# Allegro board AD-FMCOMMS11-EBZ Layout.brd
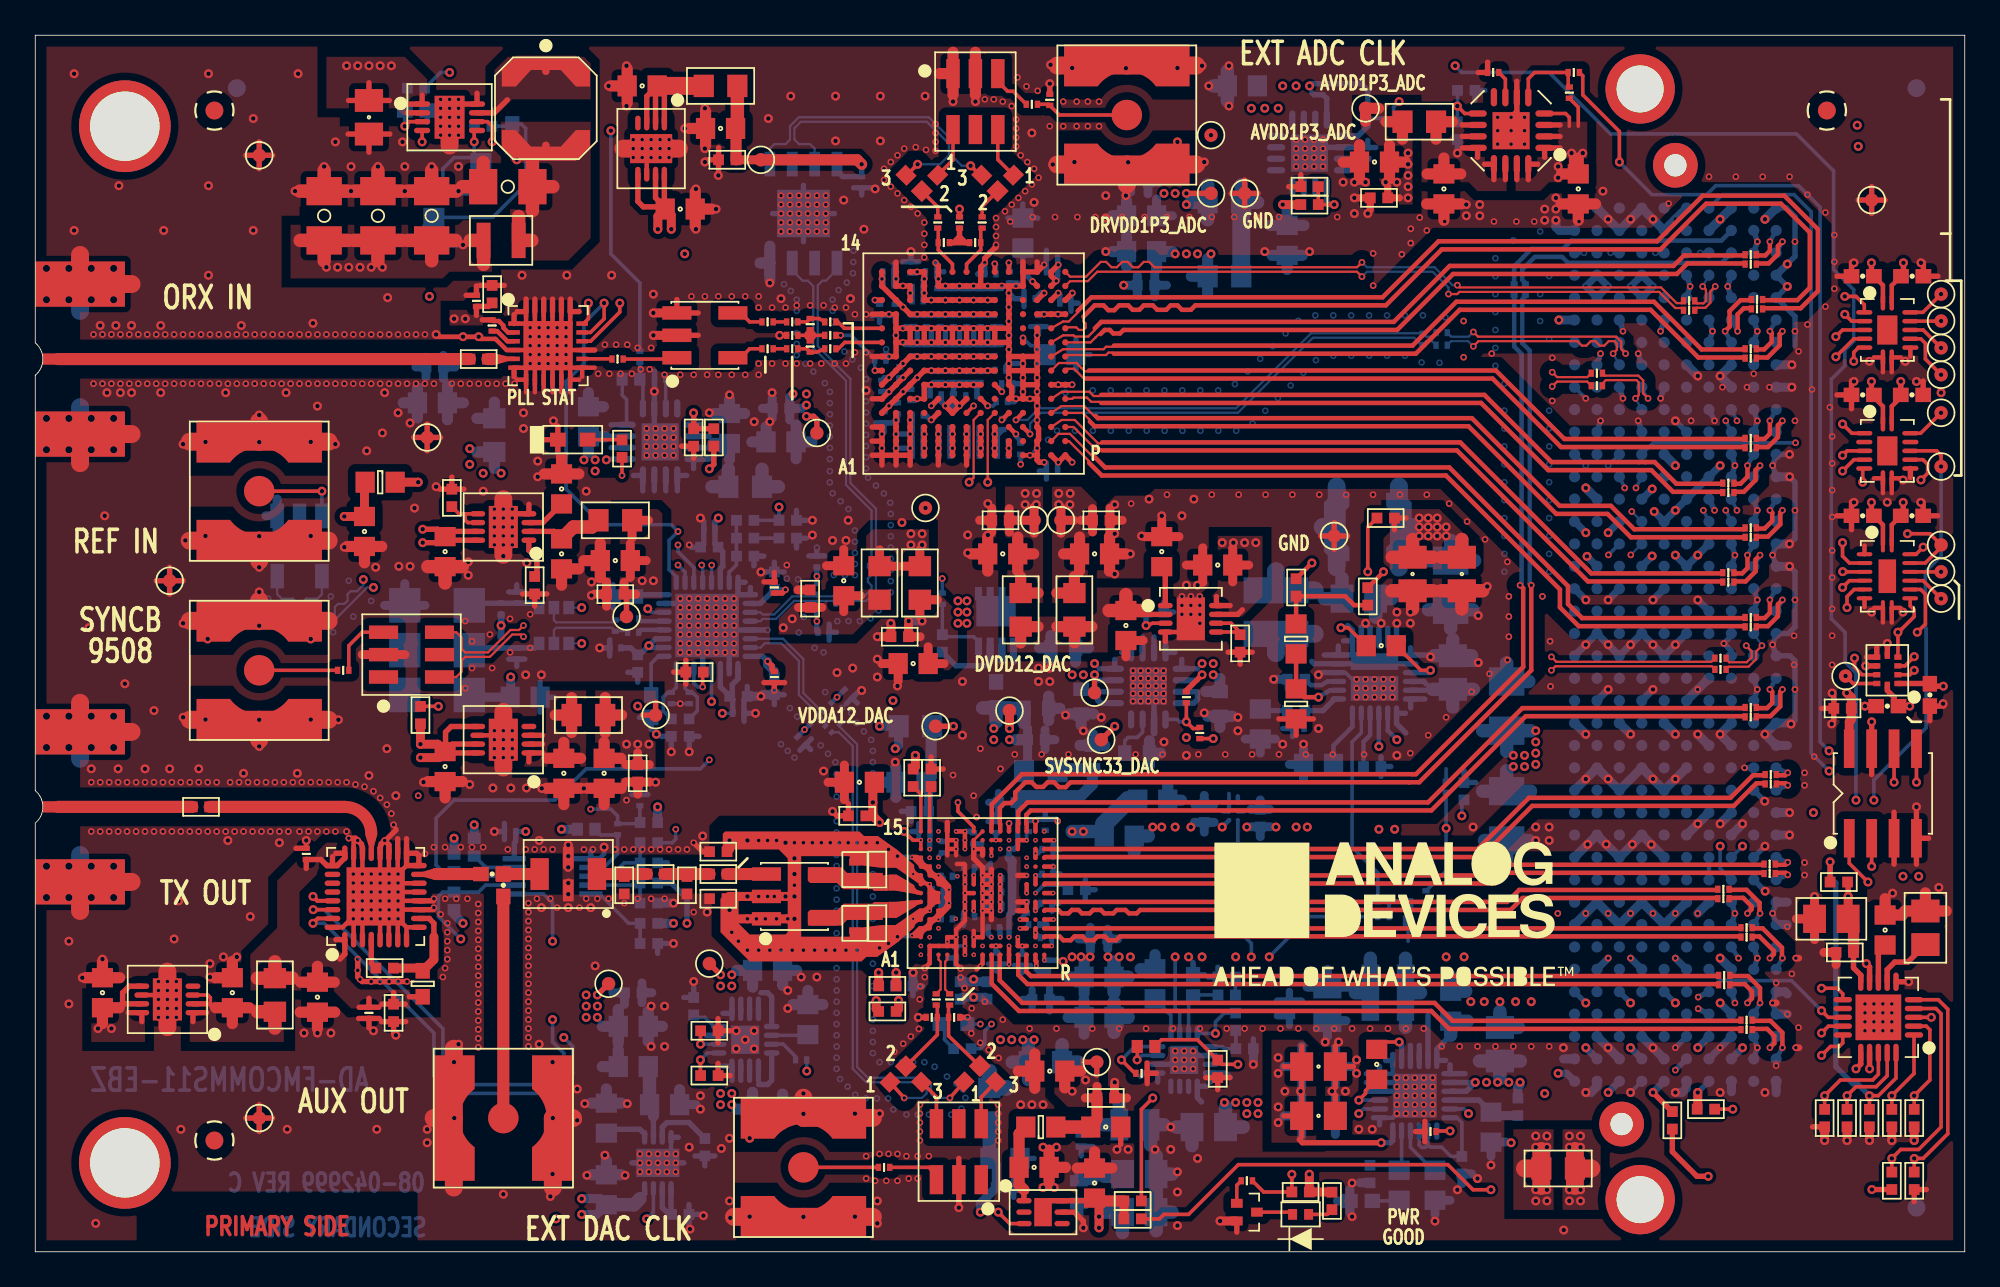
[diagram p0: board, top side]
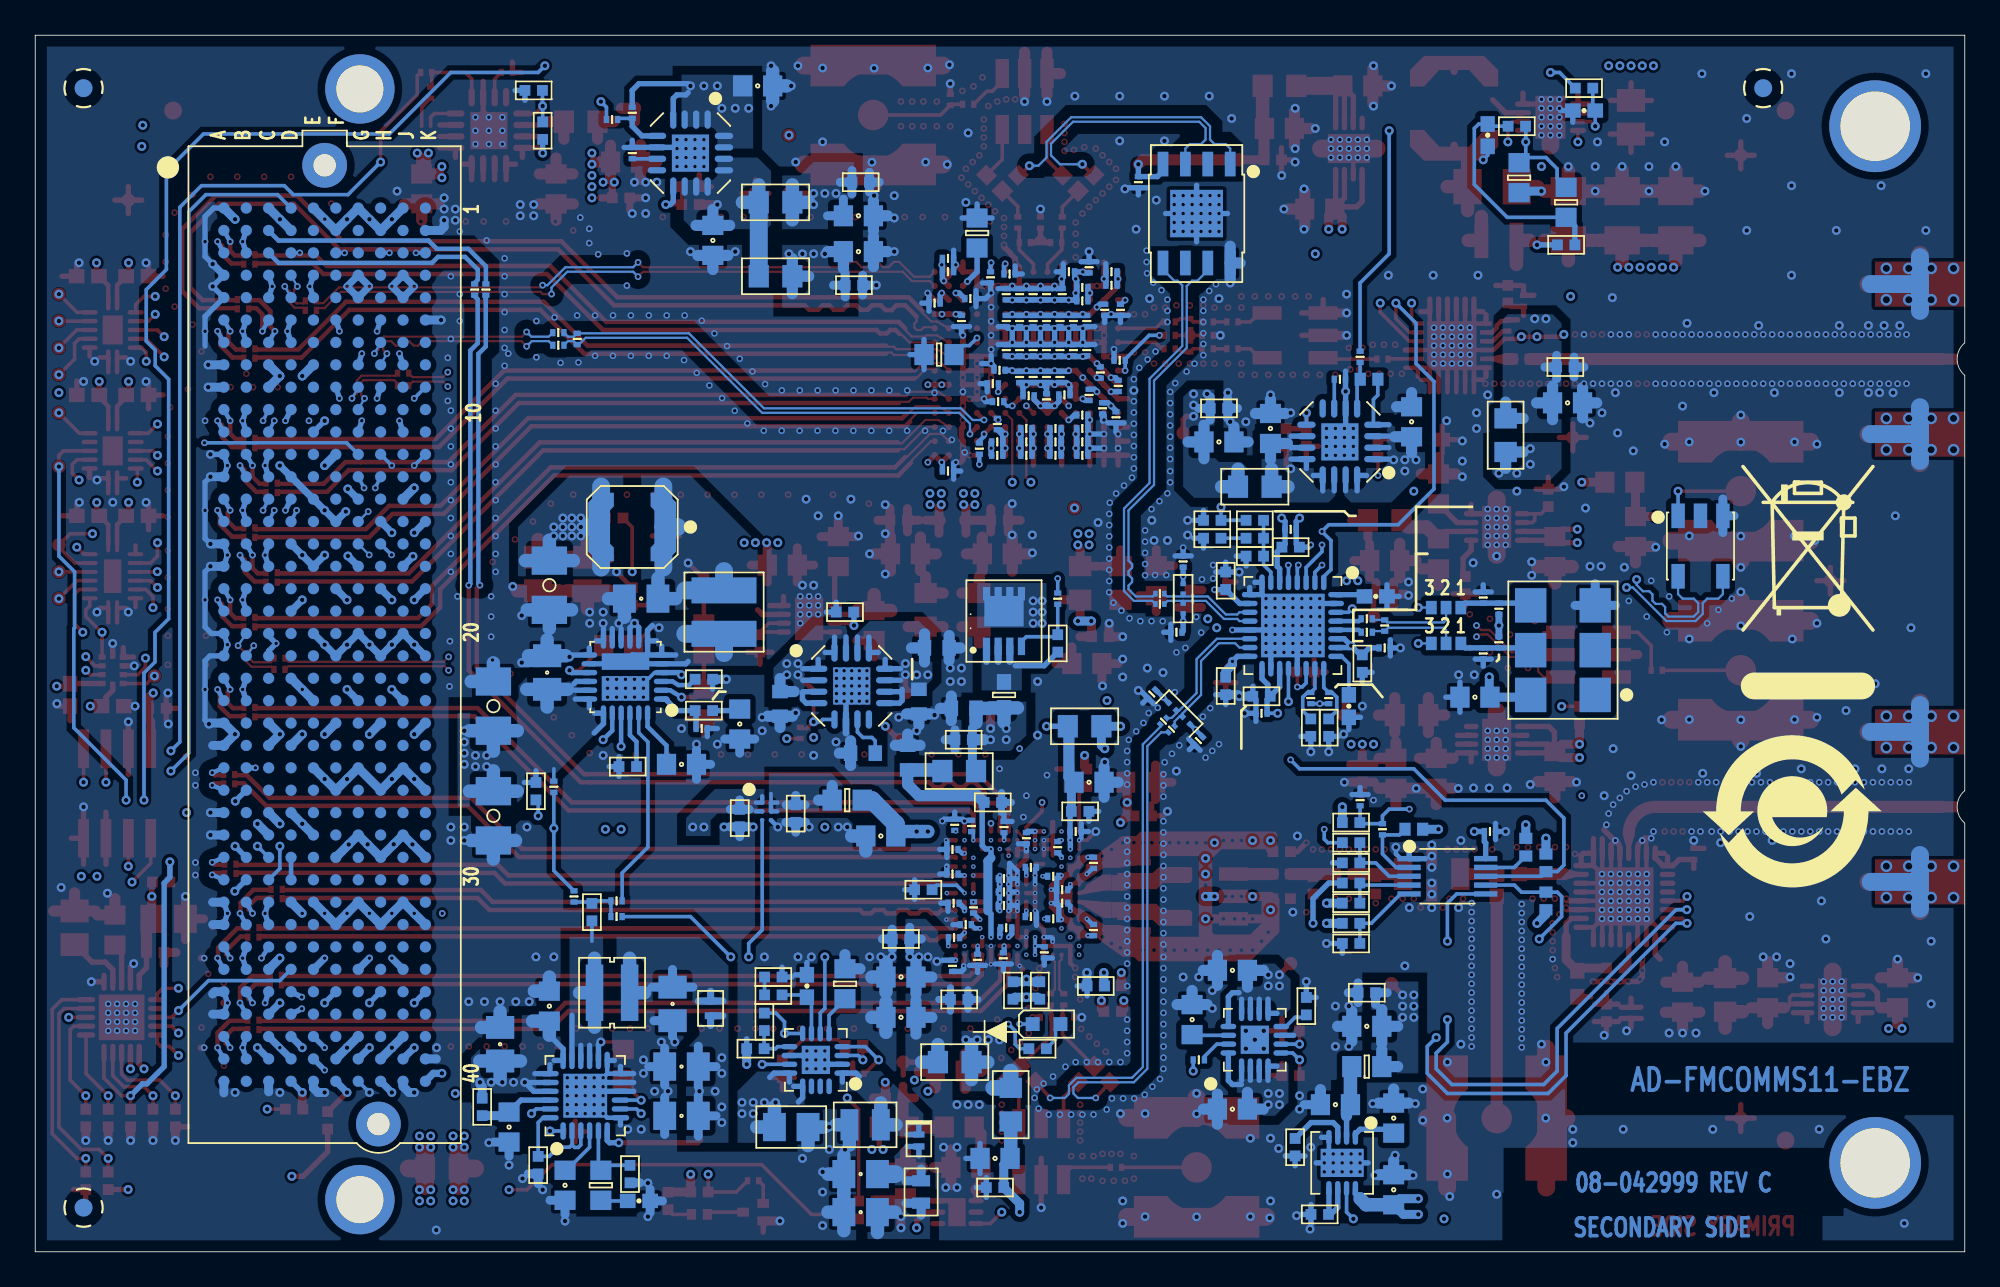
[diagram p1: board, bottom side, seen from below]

Outline 109.42 x 69 mm; copper layers: TOP, L2_GROUND, L3_SIGNAL, L4_GROUND, L5_POWER, L6_GROUND, L7_GROUND, L8_POWER, L9_GROUND, L10_SIGNAL, L11_GROUND, BOTTOM. Coordinates in mm from the lower left corner of the outline.
Outline path: 0,69 109.42,69 109.42,0 0,0 0,24.31 arc(0.43,25.23) 0,26.15 0,49.71 arc(0.43,50.63) 0,51.55 0,69

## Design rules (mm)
constraint set DEFAULT: min track width 0.203
net group ADC_CLK: nets ADC_CLK_N ADC_CLK_P
net group ADC_CLK2: nets UNNAMED_28_HMC361_I1297_OUT UNNAMED_28_HMC361_I1297_OUTN
net group ADC_CLK3: nets UNNAMED_28_ADF4355_I1290_RFOU_1 UNNAMED_28_ADF4355_I1290_RFOUTA
net group DAC_CLK3: nets UNNAMED_28_ADF4355_I1290_RFOU_2 UNNAMED_28_ADF4355_I1290_RFOUTB
net group DAC_CLK_N: nets DAC_CLK_N UNNAMED_28_CAP_I1301_N1
net group DAC_CLK_P: nets DAC_CLK_P UNNAMED_28_CAP_I1302_N1
net group DAC_OUT: nets DAC_OUT_N DAC_OUT_P
net group DIVCLK_N: nets DIVCLK_N UNNAMED_27_CAP_I500_N2
net group DIVCLK_P: nets DIVCLK_P UNNAMED_27_CAP_I499_N2
net group DOUTA_N: nets DOUTA_N UNNAMED_27_CAP_I377_N2
net group DOUTA_P: nets DOUTA_P UNNAMED_27_CAP_I378_N2
net group DOUTB_N: nets DOUTB_N UNNAMED_27_CAP_I363_N2
net group DOUTB_P: nets DOUTB_P UNNAMED_27_CAP_I362_N2
net group DOUTC_N: nets DOUTC_N UNNAMED_27_CAP_I364_N2
net group DOUTC_P: nets DOUTC_P UNNAMED_27_CAP_I365_N2
net group DOUTD_N: nets DOUTD_N UNNAMED_27_CAP_I366_N2
net group DOUTD_P: nets DOUTD_P UNNAMED_27_CAP_I367_N2
net group DOUTE_N: nets DOUTE_N UNNAMED_27_CAP_I373_N2
net group DOUTE_P: nets DOUTE_P UNNAMED_27_CAP_I374_N2
net group DOUTF_N: nets DOUTF_N UNNAMED_27_CAP_I369_N2
net group DOUTF_P: nets DOUTF_P UNNAMED_27_CAP_I368_N2
net group DOUTG_N: nets DOUTG_N UNNAMED_27_CAP_I376_N2
net group DOUTG_P: nets DOUTG_P UNNAMED_27_CAP_I375_N2
net group DOUTH_N: nets DOUTH_N UNNAMED_27_CAP_I371_N2
net group DOUTH_P: nets DOUTH_P UNNAMED_27_CAP_I370_N2
net group DP1: nets UNNAMED_28_CAP_I1359_N2 UNNAMED_28_CAP_I1360_N2
net group DP2: nets UNNAMED_28_CAP_I1372_N2 UNNAMED_28_CAP_I1373_N2
net group DP3: nets UNNAMED_28_NC3PJMPR_I1389_B UNNAMED_28_NC3PJMPR_I1390_B
net group DSYNC_P1: nets DSYNC_P1_N DSYNC_P1_P
net group DUT_DSYNC: nets DUT_DSYNC_N DUT_DSYNC_P
net group FPGA_CLK: nets FPGA_CLK_N FPGA_CLK_P
net group PLL_REF_IN: nets PLL_REF_IN_N PLL_REF_IN_P
net group SERDIN0_N: nets SERDIN0_N UNNAMED_27_CAP_I475_N2
net group SERDIN0_P: nets SERDIN0_P UNNAMED_27_CAP_I476_N2
net group SERDIN1_N: nets SERDIN1_N UNNAMED_27_CAP_I462_N2
net group SERDIN1_P: nets SERDIN1_P UNNAMED_27_CAP_I461_N2
net group SERDIN2_N: nets SERDIN2_N UNNAMED_27_CAP_I473_N2
net group SERDIN2_P: nets SERDIN2_P UNNAMED_27_CAP_I474_N2
net group SERDIN3_N: nets SERDIN3_N UNNAMED_27_CAP_I464_N2
net group SERDIN3_P: nets SERDIN3_P UNNAMED_27_CAP_I463_N2
net group SERDIN4_N: nets SERDIN4_N UNNAMED_27_CAP_I470_N2
net group SERDIN4_P: nets SERDIN4_P UNNAMED_27_CAP_I469_N2
net group SERDIN5_N: nets SERDIN5_N UNNAMED_27_CAP_I472_N2
net group SERDIN5_P: nets SERDIN5_P UNNAMED_27_CAP_I471_N2
net group SERDIN6_N: nets SERDIN6_N UNNAMED_27_CAP_I466_N2
net group SERDIN6_P: nets SERDIN6_P UNNAMED_27_CAP_I465_N2
net group SERDIN7_N: nets SERDIN7_N UNNAMED_27_CAP_I468_N2
net group SERDIN7_P: nets SERDIN7_P UNNAMED_27_CAP_I467_N2
net group SYNC_DAC_N: nets SYNC_DAC_N UNNAMED_27_CN400PAKV2_I439_LA03
net group SYNC_DAC_P: nets SYNC_DAC_P UNNAMED_27_CN400PAKV2_I439_LA_1
net group UNNAMED_14_CAP_I121_N1: nets UNNAMED_14_ADP5073_I95_COMP UNNAMED_14_CAP_I121_N1
net group UNNAMED_21_CAP_I99_N2: nets UNNAMED_21_ADL5240_I13_DSAOUT UNNAMED_21_CAP_I99_N2
net group UNNAMED_21_CAP_I102_N1: nets UNNAMED_21_CAP_I102_N1 UNNAMED_21_CAP_I102_N2
net group UNNAMED_28_CAP_I1252_N1: nets UNNAMED_28_CAP_I1252_N1 UNNAMED_28_CAP_I1252_N2
net group UNNAMED_28_CAP_I1313_N1: nets UNNAMED_28_CAP_I1313_N1 UNNAMED_28_CAP_I1314_N1
net group UNNAMED_28_CAP_I1380_N1: nets UNNAMED_28_CAP_I1380_N1 UNNAMED_28_CAP_I1380_N2
net group UNNAMED_14_CAP_I5_N1: nets UNNAMED_14_CAP_I5_N1

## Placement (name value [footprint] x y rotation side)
C1  100pF  [C0402]  38.73 22.69 180 top
C2  100pF  [C0402]  38.73 21.42 180 top
C3  100pF  [C0402]  38.73 20.03 180 top
C4  10pF  [C0402]  37.08 29.73 270 bottom
C5  0.1uF  [C0201]  37.08 31.41 270 bottom
C6  1UF  [C0402]  59.05 20.53 0 bottom
C7  100pF  [C0402]  19.81 16.09 0 top
C8  0.1uF  [C0201]  51.43 22.95 90 bottom
C9  0.1uF  [C0201]  15.37 22.57 90 top
C10  1UF  [C0402]  50.8 26.88 90 top
C11  0.6pF  [C0201]  44.98 29.64 315 bottom
C12  0.6pF  [C0201]  45.44 30.1 315 bottom
C13  100pF  [C0201]  43.46 28.99 315 bottom
C14  0.1uF  [C0201]  36.07 31.41 270 bottom
C15  0.1uF  [C0201]  32.89 34.25 180 bottom
C16  10pF  [C0402]  38.23 39.97 180 bottom
C17  0.1uF  [C0201]  38.23 40.98 180 bottom
C18  0.01UF  [C0603]  27.77 31.46 0 bottom
C19  100pF  [C0402]  9.4 25.23 180 top
C20  100pF  [C0402]  20.32 13.55 270 top
C21  0.001uF  [C0201]  18.92 13.55 270 top
C22  22UF  [C0805H60]  18.92 64.35 90 top
C23  22UF  [C0805H60]  80.39 32.85 270 bottom
C24  68PF  [C0402#2]  65.66 15.07 90 bottom
C25  0.1UF  [C0402#2]  34.92 30.95 270 bottom
C26  0.022uF  [C0603]  72.77 27.65 180 bottom
C27  10uF  [C0805H53]  66.55 7.07 0 bottom
C28  0.056uF  [C0402]  67.56 15.58 180 bottom
C29  220pF  [C0402]  25.4 63.84 180 bottom
C30  0.1UF  [C0402#2]  33.4 37.17 180 bottom
C31  1UF  [C0402]  71.5 32.47 180 bottom
C32  0.001uF  [C0201]  95.57 33.03 0 top
C33  0.01UF  [C0402#2]  27.05 63.33 270 bottom
C34  0.001uF  [C0201]  95.57 33.67 0 top
C35  680pF  [C0201]  71.63 29.68 180 bottom
C36  100pF  [C0201]  46.1 31.63 315 bottom
C37  0.0068uF  [C0603]  69.47 29.93 270 bottom
C38  22uF  [C1206H71]  26.8 60.41 0 top
C39  0.1UF  [C0603H62]  76.33 34.38 0 top
C40  100pF  [C0402]  71.5 37.68 90 top
C41  0.001uF  [C0201]  17.46 32.98 0 top
C42  47uF  [C0805H60]  75.06 37.04 180 bottom
C43  22uF  [C1206H71]  16.38 58.76 270 top
C44  0.001uF  [C0201]  56.65 18.55 180 bottom
C45  22uF  [C1206H71]  22.48 58.76 270 top
C46  1UF  [C0402]  68.58 11.52 0 bottom
C47  1UF  [C0402]  67.06 10.37 270 top
C48  22UF  [C0805H60]  62.61 4.41 180 bottom
C49  0.47uF  [C0402]  49.28 15.07 180 bottom
C50  22uF  [C1206H71]  19.43 58.76 270 top
C51  100uF  [C1206H71]  80.26 37.81 90 bottom
C52  47uF  [C0805H60]  62.61 2.25 180 bottom
C53  47uF  [C0805H60]  78.11 38.44 90 top
C54  47uF  [C0805H60]  80.9 38.44 90 top
C55  0.022uF  [C0603]  79.38 3.77 90 bottom
C56  47uF  [C0805H60]  83.06 11.77 270 bottom
C57  10UF  [C0603]  80.26 13.93 270 bottom
C58  0.1UF  [C0603H62]  82.55 7.07 90 bottom
C59  1uF  [C0402]  80.9 4.91 90 bottom
C60  470pF  [C0402]  75.69 4.41 270 bottom
C61  0.1UF  [C0603H62]  76.07 10.63 270 top
C62  22UF  [C0805H60]  73.28 14.06 90 bottom
C63  10uF  [C0603]  32.38 3.52 90 bottom
C64  0.0022uF  [C0402#2]  75.18 2.88 180 bottom
C65  22UF  [C0805H60]  72.77 10.5 180 bottom
C66  1UF  [C0402]  37.97 5.93 90 bottom
C67  22UF  [C0805H60]  72.77 7.71 180 bottom
C68  10uF  [C0603]  32.38 7.58 90 bottom
C69  22UF  [C0805H60]  72.77 10.5 180 top
C70  1UF  [C0402]  69.47 24.6 270 bottom
C71  100PF  [C0402]  51.43 34.5 270 bottom
C72  22UF  [C0805H60]  72.77 7.71 180 top
C73  0.1UF  [C0402#2]  21.59 64.73 0 bottom
C74  1UF  [C0402]  36.58 2.12 0 bottom
C75  1.5NF  [C0402]  40.26 39.46 0 bottom
C76  0.033uF  [C0402]  40.26 40.47 0 bottom
C77  10uF  [C0603]  35.69 8.34 0 bottom
C78  0.47uF  [C0402]  46.61 24.73 180 top
C79  0.47uF  [C0402]  48.32 15.08 0 top
C80  1UF  [C0402]  66.29 24.85 270 bottom
C81  10pF  [C0402]  36.07 29.73 270 bottom
C82  10uF  [C0603#2]  56.77 30.82 0 bottom
C83  0.1UF  [C0402]  102.49 30.82 180 top
C84  10uF  [C0603]  49.66 26.63 180 bottom
C85  10uF  [C0603#2]  58.29 34.25 180 bottom
C86  0.01UF  [C0603]  43.81 13.17 90 bottom
C87  10uF  [C0603]  33.91 12.79 0 bottom
C88  10uF  [C0603]  61.47 23.58 0 bottom
C89  10uF  [C0603]  18.67 40.85 270 top
C90  0.1UF  [C0402#2]  103.63 41.74 0 top
C91  0.1UF  [C0402]  56.77 29.04 0 bottom
C92  0.1UF  [C0402#2]  107.44 31.58 90 top
C93  0.1UF  [C0402]  50.16 24.98 180 bottom
C94  0.1UF  [C0402#2]  103.63 55.33 0 top
C95  10uF  [C0603]  41.53 8.09 0 bottom
C96  0.1UF  [C0402]  33.91 14.69 0 bottom
C97  0.1UF  [C0402#2]  103.63 48.6 0 top
C98  0.1UF  [C0402#2]  105.03 30.95 0 top
C99  4.7uF  [C0603]  3.81 14.69 90 top
C100  0.1uF  [C0201]  26.92 23.84 180 bottom
C101  4.7uF  [C0603]  11.18 14.69 90 top
C102  10uF  [C0603]  16 14.44 270 top
C103  0.1UF  [C0402#2]  106.44 55.33 180 top
C104  0.001uF  [C0201]  56.21 19.53 270 bottom
C105  0.1uF  [C0201]  55.24 55.27 270 bottom
C106  4.7uF  [C0603]  60.32 15.58 0 bottom
C107  0.1uF  [C0201]  51.69 21.3 180 bottom
C108  0.1uF  [C0201]  57.4 21.42 0 bottom
C109  0.1uF  [C0201]  49.4 22.06 90 bottom
C110  0.1uF  [C0201]  51.69 18.88 180 bottom
C111  0.1uF  [C0201]  57.34 19.77 0 bottom
C112  0.1uF  [C0201]  49.4 18.25 270 bottom
C113  0.1uF  [C0201]  51.18 19.77 0 bottom
C114  0.1uF  [C0201]  51.18 20.53 0 bottom
C115  0.1uF  [C0201]  57.32 17.82 0 bottom
C116  0.1uF  [C0201]  52.96 19.01 180 bottom
C117  4.7uF  [C0603]  57.53 10.25 0 top
C118  0.1uF  [C0201]  57.28 24.22 90 bottom
C119  4.7uF  [C0603]  46.74 26.63 180 top
C120  0.1uF  [C0201]  54.48 20.41 180 bottom
C121  0.1uF  [C0201]  57.4 22.82 0 bottom
C122  0.47uF  [C0402]  60.32 17.74 0 bottom
C123  0.1uF  [C0201]  54.48 19.65 180 bottom
C124  0.1uF  [C0201]  52.96 21.8 180 bottom
C125  0.1UF  [C0402#2]  106.43 41.74 180 top
C126  0.1UF  [C0402#2]  106.43 48.6 180 top
C127  0.1uF  [C0201]  56.52 65.09 180 top
C128  4.7uF  [C0603]  104.9 18.25 270 top
C129  0.1UF  [C0402]  102.62 16.98 0 top
C130  0.1uF  [C0201]  57.4 16.22 270 bottom
C131  0.1uF  [C0201]  54.48 21.17 180 bottom
C132  0.1uF  [C0201]  54.48 24.09 90 bottom
C133  0.1uF  [C0201]  56.32 24.15 90 bottom
C134  0.1uF  [C0201]  54.52 16.64 270 bottom
C135  0.1uF  [C0201]  50.42 23.84 180 bottom
C136  0.1uF  [C0201]  55.98 16.56 270 bottom
C137  0.1uF  [C0201]  53.21 23.46 270 bottom
C138  0.1uF  [C0201]  52.2 16.98 270 bottom
C139  10uF  [C0603]  23.24 39.71 270 top
C140  10uF  [C0603]  23.24 27.52 270 top
C141  0.1uF  [C0201]  54.17 55.46 180 bottom
C142  4.7uF  [C0603]  36.58 59.14 0 top
C143  10uF  [C0603]  29.84 43.27 90 top
C144  0.1uF  [C0201]  47.88 53.43 270 bottom
C145  1UF  [C0402]  28.32 37.81 270 top
C146  1UF  [C0402]  23.62 42.76 90 top
C147  10uF  [C0603]  29.84 39.58 270 top
C148  10uF  [C0603]  29.97 27.14 270 top
C149  100pF  [C0402#2]  25.91 21.42 180 top
C150  4.7uF  [C0603]  34.42 66.13 180 top
C151  10uF  [C0603]  45.85 38.06 90 top
C152  10uF  [C0603]  32.89 39.2 180 top
C153  10uF  [C0603]  32.26 27.14 270 top
C154  10uF  [C0805H53]  101.85 18.88 180 top
C155  100pF  [C0402#2]  26.54 20.79 90 top
C156  10uF  [C0805H53]  107.19 18.38 270 top
C157  10uF  [C0603]  38.86 63.71 180 top
C158  0.1UF  [C0402]  43.94 37.04 90 top
C159  0.1UF  [C0402]  32.89 37.3 180 top
C160  0.1UF  [C0402]  34.16 27.14 270 top
C161  47UF  [C1206H71]  83.44 24.73 270 bottom
C163  47UF  [C1206H71]  83.44 30.95 90 bottom
C164  0.1UF  [C0402]  39.24 61.94 180 top
C165  0.001uF  [C0201]  97.28 30.87 0 top
C166  0.001uF  [C0201]  97.28 30.34 0 top
C167  0.001uF  [C0201]  98.35 21.99 0 top
C168  0.001uF  [C0201]  98.35 21.45 0 top
C169  0.001uF  [C0201]  97.05 12.6 0 top
C170  0.001uF  [C0201]  97.05 13.14 0 top
C171  0.001uF  [C0201]  95.73 20.03 0 top
C172  0.001uF  [C0201]  95.73 20.56 0 top
C173  0.001uF  [C0201]  83.86 54.58 90 bottom
C174  0.001uF  [C0201]  84.5 54.58 90 bottom
C175  0.001uF  [C0201]  98.42 27.07 0 top
C176  0.001uF  [C0201]  98.42 26.53 0 top
C177  0.001uF  [C0201]  97.05 17.85 0 top
C178  0.001uF  [C0201]  97.05 18.38 0 top
C179  0.001uF  [C0201]  95.78 15.14 0 top
C180  0.001uF  [C0201]  95.78 15.68 0 top
C183  0.47uF  [C0402]  53.98 14.82 270 bottom
C184  0.47uF  [C0402]  52.45 14.82 270 bottom
C185  0.47uF  [C0402]  48.32 13.63 0 top
C186  0.1uF  [C0201]  33.91 35.14 0 bottom
C187  0.1uF  [C0201]  33.91 35.9 0 bottom
C188  1pF  [C0201]  52.11 13.3 0 top
C189  1pF  [C0201]  50.84 13.3 180 top
C190  0.001uF  [C0201]  51.85 14.31 90 top
C191  0.001uF  [C0201]  51.09 14.31 90 top
C194  4.7uF  [C0603#2]  67.18 31.08 270 bottom
C195  0.01UF  [C0603#2]  62.48 28.28 0 bottom
C196  0.1uF  [C0201]  58.42 53.81 0 bottom
C197  0.1uF  [C0201]  47.92 50.56 0 bottom
C198  0.1uF  [C0201]  51.31 49.62 270 bottom
C199  0.1uF  [C0201]  50.04 47.46 180 bottom
C200  0.1uF  [C0201]  52.07 49.62 270 bottom
C201  0.1uF  [C0201]  53.7 58.38 270 top
C202  0.1uF  [C0201]  51.18 58.38 270 top
C203  0.1uF  [C0201]  52.41 58.38 270 top
C204  0.001uF  [C0201]  48.13 4.79 0 top
C205  4.7uF  [C0603]  68.45 66.13 180 bottom
C206  4.7uF  [C0603]  87.5 60.29 270 top
C207  0.01uF  [C0201]  75.56 62.32 90 bottom
C208  0.001uF  [C0201]  97.28 56.55 0 top
C209  0.001uF  [C0201]  97.28 56.02 0 top
C210  0.001uF  [C0201]  97.28 51.22 0 top
C211  0.001uF  [C0201]  97.28 50.68 0 top
C212  0.001uF  [C0201]  97.28 46.14 0 top
C213  0.001uF  [C0201]  97.28 45.6 0 top
C214  0.001uF  [C0201]  97.28 41.06 0 top
C215  0.001uF  [C0201]  97.28 40.52 0 top
C216  0.001uF  [C0201]  97.28 35.98 0 top
C217  0.001uF  [C0201]  97.28 35.44 0 top
C218  0.001uF  [C0201]  96.01 43.6 0 top
C219  0.001uF  [C0201]  96.01 43.06 0 top
C220  0.001uF  [C0201]  96.01 38.52 0 top
C221  0.001uF  [C0201]  96.01 37.98 0 top
C222  0.001uF  [C0201]  97.64 53.48 180 top
C223  0.001uF  [C0201]  97.64 54.01 180 top
C226  0.01uF  [C0201]  82.68 66.89 180 top
C227  4.7uF  [C0603]  70.99 57.36 270 bottom
C228  4.7uF  [C0603]  79.88 60.29 270 top
C229  10uF  [C0603]  75.95 61.81 180 top
C230  10uF  [C0603]  62.74 58.76 180 bottom
C231  10uF  [C0603]  62.74 56.73 180 bottom
C232  10uF  [C0603]  49.78 33.36 180 top
C233  10uF  [C0603]  22.52 48.15 180 bottom
C234  0.1UF  [C0402]  76.2 59.78 180 top
C235  0.1UF  [C0402]  62.61 60.67 180 bottom
C236  0.1UF  [C0402]  62.99 54.82 180 bottom
C237  0.1UF  [C0402]  49.02 34.89 180 top
C238  0.1UF  [C0402]  22.65 50.18 180 bottom
C239  0.001uF  [C0201]  93.79 53.94 0 top
C240  0.001uF  [C0201]  93.79 53.4 0 top
C241  4.7uF  [C0603#2]  59.31 31.2 270 bottom
C242  0.6pF  [C0201]  45.64 36.74 0 bottom
C243  10uF  [C0603]  67.06 38.95 180 top
C244  4.7uF  [C0603]  31.37 47.08 90 bottom
C245  1UF  [C0402]  63.5 36.28 180 bottom
C246  0.01uF  [C0201]  35.43 49.49 180 bottom
C247  10uF  [C0603]  63.88 39.71 90 top
C248  1UF  [C0402]  68.33 34.5 270 top
C249  4.7uF  [C0603]  39.37 46.7 90 bottom
C250  10uF  [C0603]  61.85 35.52 270 top
C251  10uF  [C0603]  60.07 39.58 0 top
C252  10uF  [C0603]  54.86 39.58 180 top
C253  10uF  [C0603]  42.29 45.93 180 bottom
C254  0.1UF  [C0402]  60.45 41.49 0 top
C255  0.1UF  [C0402]  54.74 41.49 180 top
C256  0.1UF  [C0402]  42.29 47.84 180 bottom
C257  0.1uF  [C0201]  49.78 52.79 270 bottom
C258  0.1uF  [C0201]  54.74 50 0 bottom
C259  0.1uF  [C0201]  50.55 52.79 270 bottom
C260  0.1uF  [C0201]  57.66 56.35 180 bottom
C261  0.1uF  [C0201]  51.31 52.79 270 bottom
C262  0.1uF  [C0201]  49.66 48.6 270 bottom
C263  0.1uF  [C0201]  57.66 55.59 180 bottom
C264  0.1uF  [C0201]  52.07 52.79 270 bottom
C265  0.6pF  [C0201]  45.64 37.32 0 bottom
C266  0.1uF  [C0201]  54.86 45.93 180 bottom
C267  0.1uF  [C0201]  52.83 52.79 270 bottom
C268  0.1uF  [C0201]  53.59 49.62 270 bottom
C269  0.1uF  [C0201]  54.86 45.17 180 bottom
C270  0.1uF  [C0201]  53.59 52.79 270 bottom
C271  0.1uF  [C0201]  57.66 44.28 180 bottom
C272  0.1uF  [C0201]  48.89 47.84 270 bottom
C273  0.1uF  [C0201]  51.56 46.7 180 bottom
C274  0.1uF  [C0201]  54.36 52.79 270 bottom
C275  0.1uF  [C0201]  48.13 47.33 270 bottom
C276  0.1uF  [C0201]  56.9 52.79 270 bottom
C277  0.1uF  [C0201]  51.56 45.93 180 bottom
C278  0.1uF  [C0201]  48.39 55.59 0 bottom
C279  0.1uF  [C0201]  50.04 53.94 180 bottom
C280  0.1uF  [C0201]  51.56 45.17 180 bottom
C281  0.1uF  [C0201]  49.78 51.14 90 bottom
C282  0.1uF  [C0201]  53.09 48.55 0 bottom
C283  0.1uF  [C0201]  54.36 54.32 90 bottom
C284  0.1uF  [C0201]  50.04 46.7 180 bottom
C285  0.1uF  [C0201]  50.55 51.14 90 bottom
C286  0.1uF  [C0201]  52.07 48.35 90 bottom
C287  0.1uF  [C0201]  49.66 55.84 90 bottom
C288  0.1uF  [C0201]  50.04 45.93 180 bottom
C289  0.1uF  [C0201]  51.31 51.14 90 bottom
C290  0.1uF  [C0201]  52.83 49.62 270 bottom
C291  0.1uF  [C0201]  51.05 48.6 180 bottom
C292  0.1uF  [C0201]  50.04 45.17 180 bottom
C293  0.1uF  [C0201]  52.07 51.14 90 bottom
C294  0.1uF  [C0201]  50.04 54.7 180 bottom
C295  0.1uF  [C0201]  53.21 46.7 180 bottom
C296  0.1uF  [C0201]  52.83 51.14 90 bottom
C297  0.1uF  [C0201]  52.83 54.32 90 bottom
C298  0.1uF  [C0201]  53.21 45.93 180 bottom
C299  0.1uF  [C0201]  53.59 51.14 90 bottom
C300  0.1uF  [C0201]  50.8 55.59 0 bottom
C301  0.1uF  [C0201]  53.21 45.17 180 bottom
C302  0.1uF  [C0201]  54.36 51.14 90 bottom
C303  0.1uF  [C0201]  51.18 54.32 90 bottom
C304  0.1uF  [C0201]  48.39 54.82 0 bottom
C305  0.1uF  [C0201]  52.07 54.32 90 bottom
C306  0.1uF  [C0201]  48.01 49.11 270 bottom
C307  0.1uF  [C0201]  53.59 54.32 90 bottom
C308  0.1uF  [C0201]  49.02 49.87 270 bottom
C309  0.1uF  [C0201]  48.77 53.43 270 bottom
C310  1UF  [C0402]  38.23 9.99 180 top
C311  10uF  [C0603]  60.32 13.3 0 bottom
C312  10uF  [C0603]  54.99 5.29 0 bottom
C313  10uF  [C0603#2]  59.94 28.03 90 bottom
C314  100pF  [C0201]  44.32 39.15 90 bottom
C315  100pF  [C0201]  44.7 35.14 0 bottom
C316  4.7uF  [C0603]  60.07 3.9 90 top
C317  4.7uF  [C0603]  56.64 4.79 0 top
C318  0.1uF  [C0201]  41.53 51.22 0 top
C319  0.1uF  [C0201]  41.53 52.74 0 top
C320  0.1uF  [C0201]  42.93 51.98 0 top
C321  10uF  [C0603]  60.71 7.07 0 top
C322  0.1UF  [C0402]  60.71 8.72 0 top
C323  100pF  [C0402]  25.15 50.63 0 top
C324  100pF  [C0201]  33.02 50.63 0 top
C326  0.1uF  [C0201]  39.88 30.54 0 bottom
C327  10pF  [C0402]  39.88 31.51 0 bottom
C328  10pF  [C0402]  34.16 33.36 270 bottom
C329  0.1uF  [C0201]  41.91 32.6 270 top
C330  10pF  [C0402]  41.91 32.09 270 bottom
C331  0.1uF  [C0201]  41.91 37.68 90 top
C332  10pF  [C0402]  41.91 38.06 90 bottom
C333  0.001uF  [C0201]  46.86 60.67 270 bottom
C334  1UF  [C0402]  38.23 12.53 180 top
C335  0.1UF  [C0402]  57.02 14.31 180 bottom
C336  390PF  [C0402]  42.67 41.49 0 bottom
C337  100pF  [C0402]  25.91 54.32 90 top
C338  0.001uF  [C0201]  25.02 53.94 90 top
C339  0.1UF  [C0402]  54.99 3.64 0 bottom
C340  0.1UF  [C0402]  55.12 25.49 180 bottom
C341  10uF  [C0603]  41.53 15.96 0 bottom
CR5  LG L29K-G2J1-24-Z  [LED0603-2]  52.07 12.91 180 bottom
D2  PMEG2005AEL,315  [SOD882]  59.31 6.31 270 bottom
DS1  SML-E12M8WT86  [LED0603_A]  30.48 46.06 0 top
DS2  SML-P11MTT86  [LED0402]  71.75 2.12 0 top
E1  270nH  [L0402-2]  46.48 18.63 270 top
E2  270nH  [L0402-2]  46.48 21.68 270 top
E3  42OHM AT 100MEGHZ  [L0805]  86.36 4.72 0 top
E4  0  [R0603#2]  54.48 31.58 270 bottom
E5  33NH  [L0402-2]  71.12 13.8 270 bottom
E6  42OHM AT 100MEGHZ  [L0805]  57.02 27.27 0 bottom
E7  42OHM AT 100MEGHZ  [L0805]  49.91 29.81 0 bottom
E8  42OHM AT 100MEGHZ  [L0805]  54.1 8.34 270 bottom
E9  42OHM AT 100MEGHZ  [L0805]  57.28 10.76 0 bottom
E12  0  [R0603]  33.91 10.5 180 bottom
E13  0  [R0603]  63.37 25.61 180 bottom
E14  0  [R0603]  19.56 43.65 180 top
E15  42OHM AT 100MEGHZ  [L0805]  13.59 14.57 90 top
E16  42OHM AT 100MEGHZ  [L0805]  47.88 37.93 270 top
E17  42OHM AT 100MEGHZ  [L0805]  32.89 41.49 0 top
E18  42OHM AT 100MEGHZ  [L0805]  31.37 30.44 0 top
E21  0  [R0603]  57.02 7.07 0 top
E22  42OHM AT 100MEGHZ  [L0805]  38.86 66.13 0 top
E23  42OHM AT 100MEGHZ  [L0805]  78.49 64.1 180 top
E24  42OHM AT 100MEGHZ  [L0805]  67.44 59.52 180 bottom
E25  42OHM AT 100MEGHZ  [L0805]  67.44 55.33 180 bottom
E26  42OHM AT 100MEGHZ  [L0805]  50.16 37.93 270 top
E27  42OHM AT 100MEGHZ  [L0805]  26.03 46.32 90 bottom
E28  42OHM AT 100MEGHZ  [L0805]  58.93 36.41 90 top
E29  42OHM AT 100MEGHZ  [L0805]  55.88 36.41 90 top
E30  42OHM AT 100MEGHZ  [L0805]  40.26 43.39 0 bottom
FL1  4400MEGHZ  [FLSML126W63H37-2]  30.23 21.42 180 top
J1  142-0711-201  [CNJOHNSON142-0711-201]  12.7 43.14 90 top
J2  142-0711-201  [CNJOHNSON142-0711-201]  61.9 64.48 270 top
J3  142-0711-201  [CNJOHNSON142-0711-201]  43.56 4.79 270 top
J4  142-0701-851  [CNSMAL562W375H166]  2.36 25.23 180 top
J5  142-0711-201  [CNJOHNSON142-0711-201]  26.54 7.58 0 top
J6  142-0701-851  [CNSMAL562W375H166]  2.36 50.63 180 top
J7  142-0711-201  [CNJOHNSON142-0711-201]  12.7 32.98 90 top
JP1  3PIN_SOLDER_JUMPER  [JPRSLD03]  29.41 36.54 0 bottom
JP2  3PIN_SOLDER_JUMPER  [JPRSLD03]  29.41 34.5 0 bottom
JP3  3PIN_JUMPER  [3PINJUMPER_0402]  50.28 60.16 315 top
JP4  3PIN_JUMPER  [3PINJUMPER_0402]  54.57 60.16 315 top
JP5  3PIN_JUMPER  [3PINJUMPER_0402]  49.37 10.52 135 top
JP22  3PIN_JUMPER  [3PINJUMPER_0402]  53.57 10.53 135 top
L1  2.2UH  [L0805_A]  62.36 7.2 180 bottom
L2  10UH  [LSMSQ189H123]  28.96 64.86 270 top
L3  1.5uH  [LSMSQ157H83]  70.36 36.28 90 bottom
L4  0.68UH  [L1008H47]  26.42 57.36 180 top
L5  0.33UH  [LSMSQ154H47_A]  75.56 41.11 0 bottom
L6  0.47UH  [L7144]  59.18 3.39 270 bottom
L7  470nH  [L0603]  21.97 15.2 270 top
L8  0.33UH  [LSMSQ118H47]  76.71 14.69 180 bottom
L13  1.5NH  [L0201H13]  44.32 36.49 270 bottom
L14  1.5NH  [L0201H13]  44.32 37.6 90 bottom
L15  1.5NH  [L0201H13]  44.93 30.92 45 bottom
L16  1.5NH  [L0201H13]  44.15 30.14 225 bottom
NOREF  -  []  24.64 50.15 0 top
NOREF#2  -  []  -45.72 -248.96 0 top
NOREF#3  -  []  34.16 52.67 0 top
NOREF#4  -  []  34.16 50.13 0 top
NOREF#5  -  []  -45.72 -248.96 0 top
NOREF#6  -  []  5.08 5.04 0 top
NOREF#7  -  []  0 69 0 top
NOREF#8  -  []  0 0 0 top
NOREF#9  -  []  -38.74 -6.77 0 top
NOREF#10  -  []  0 0 0 top
NOREF#11  -  [unnamed#2]  10.16 6.31 0 top
NOREF#12  -  [unnamed#2]  10.16 64.73 0 top
NOREF#13  -  []  286.08 -70.78 0 top
NOREF#14  -  []  48.51 -49.7 180 top
NOREF#15  -  []  0.43 25.21 0 top
NOREF#16  -  []  0 69 0 top
NOREF#17  -  []  0.43 50.71 0 top
NOREF#18  -  []  1.65 81.24 0 top
NOREF#19  -  [unnamed#2]  5.08 63.84 0 top
NOREF#20  -  []  5.08 5.04 0 top
NOREF#21  -  [unnamed#2]  91.01 2.96 0 top
NOREF#22  -  []  -45.72 -248.96 0 top
NOREF#23  -  []  109.42 0 0 top
NOREF#24  -  []  28.03 53.66 0 top
NOREF#25  -  [unnamed#2]  91.01 65.96 0 top
NOREF#26  -  [unnamed#2]  5.08 5.04 0 top
NOREF#27  -  []  50.67 126.45 0 top
NOREF#28  -  []  109.42 0 90 top
NOREF#29  -  []  24.66 52.64 0 top
NOREF#30  -  []  -32.99 78.75 0 top
NOREF#31  -  [unnamed#2]  101.6 64.73 0 top
NOREF#32  -  []  76.45 19.14 0 top
NOREF#33  -  [unnamed#2]  106.68 2.5 180 bottom
NOREF#34  -  [unnamed#2]  11.43 66 180 bottom
NOREF#35  -  [unnamed#2]  106.68 66 180 bottom
NOREF#36  -  []  -0.38 48.22 180 bottom
NOREF#37  -  []  9.78 24.98 180 bottom
P1  ASP-134488-01  [CNSAMTECASP-134488-01]  98.72 59.2 270 bottom
Q1  2N7002T  [SOT523F]  68.71 2.25 270 top
Q4  SI7102DN-T1-GE3  [Q1212-8P]  54.48 35.77 180 bottom
R1  6.04K  [R0402]  67.56 14.57 180 bottom
R2  100K  [R0402]  75.82 27.52 180 bottom
R3  36.5K  [R0603]  25.27 60.92 90 bottom
R4  210K  [R0603]  22.61 59.52 270 bottom
R5  10K  [R0201]  54.36 18.38 180 bottom
R6  1K  [R0402]  52.58 11.52 0 bottom
R7  9.76K  [R0402]  49.78 26.88 90 top
R8  100  [R0201]  32.89 35.52 270 bottom
R9  5.1K  [R0402]  37.39 32.88 0 top
R10  130  [R0201]  26.42 34.57 270 bottom
R11  140  [R0402]  33.27 45.55 270 top
R12  82  [R0201]  27.3 33.93 270 bottom
R13  10K  [R0402]  62.99 11.64 0 top
R14  4.99K  [R0402]  71.5 30.69 180 bottom
R15  10K  [R0603]  71.5 31.08 90 top
R16  15K  [R0603]  71.5 34.76 270 top
R17  50K  [R0603]  63.5 15.2 270 bottom
R18  4.22K  [R0402]  75.56 37.17 90 top
R19  115K  [R0402]  62.23 2.88 180 top
R20  7.5K  [R0402]  22.61 57.11 0 bottom
R21  10  [R0402]  77.85 19.26 90 bottom
R22  0  [R0201]  79.12 6.82 180 top
R23  0  [R0201]  76.45 19.9 180 bottom
R24  0  [R0201]  78.87 20.15 90 bottom
R25  0  [R0201]  76.45 19.01 180 bottom
R26  0  [R0201]  80.01 26.38 270 bottom
R27  0  [R0201]  62.74 10.12 0 top
R28  10  [R0402]  84.07 8.22 270 bottom
R29  6.04K  [R0603]  77.34 3.77 270 bottom
R30  10K  [R0402]  71.75 3.39 0 top
R31  100  [R0201]  68.71 4.02 180 top
R32  300  [R0402]  73.53 2.88 270 top
R33  130  [R0201]  26.42 36.47 90 bottom
R34  4.02K  [R0402]  102.28 20.97 0 top
R35  4.02K  [R0402]  104.01 7.58 90 top
R36  1K  [R0402]  76.58 41.62 0 top
R37  51  [R0201]  57.53 65.34 90 top
R38  6.04K  [R0402]  105.28 7.58 90 top
R39  25.5K  [R0402]  68.07 13.04 90 bottom
R40  4.02K  [R0402]  94.74 8.09 180 top
R41  33  [R0402]  47.75 18.63 90 top
R42  33  [R0402]  47.75 21.68 90 top
R43  3K  [R0402]  34.8 23.2 180 bottom
R44  1.2K  [R0402]  34.8 22.06 0 bottom
R45  1K  [R0402]  34.8 20.92 180 bottom
R46  1.2K  [R0402]  34.8 19.77 0 bottom
R47  4.02K  [R0402]  102.74 7.58 90 top
R48  3K  [R0402]  34.8 18.63 180 bottom
R49  1.2K  [R0402]  34.8 17.49 0 bottom
R50  6.04K  [R0402]  21.84 30.44 270 top
R51  2.26K  [R0402]  106.55 7.58 90 top
R52  10K  [R0402]  24.89 22.95 270 bottom
R53  10K  [R0402]  23.75 22.06 270 bottom
R54  10K  [R0402]  23.75 19.9 90 bottom
R55  6.34K  [R0402]  81.03 26.12 90 bottom
R56  1K  [R0402]  101.47 7.58 90 top
R57  10  [R0201]  42.93 51.22 0 top
R58  10  [R0201]  42.93 52.74 0 top
R59  33  [R0201]  43.94 51.34 90 top
R60  33  [R0201]  43.94 52.61 90 top
R61  0  [R0201]  45.09 51.98 0 top
R62  10  [R0201]  45.09 51.22 0 top
R63  10  [R0201]  45.09 52.74 0 top
R64  1K  [R0402]  105.28 4.02 270 top
R65  2.26K  [R0402]  62.23 1.87 0 top
R66  4.02K  [R0402]  92.84 7.45 90 top
R67  4.02K  [R0402]  106.55 4.02 90 top
R68  80.6K  [R0402]  21.59 66 180 bottom
R69  33  [R0201]  51.52 57.24 0 top
R70  33  [R0201]  53.3 57.24 0 top
R71  115  [R0402]  36.96 20.79 270 top
R72  0  [R0201]  76.71 64.22 180 bottom
R73  82  [R0201]  27.3 37.11 90 bottom
R75  0  [R0201]  87.25 66.89 180 top
R76  0  [R0201]  34.29 50.76 270 bottom
R77  52.3  [R0402]  35.18 21.42 180 top
R78  115  [R0402]  33.4 20.79 270 top
R79  10K  [R0201]  54.81 48.22 180 bottom
R80  0  [R0201]  88.56 49.83 0 top
R81  0  [R0201]  88.56 49.12 0 top
R82  10K  [R0201]  65.28 31.46 90 top
R83  0  [R0201]  66.04 29.42 90 top
R84  8.06K  [R0402]  37.34 13.93 270 bottom
R85  0  [R0201]  43.43 10.88 180 bottom
R89  100  [R0201]  51.43 37.04 270 bottom
R91  0  [R0201]  33.02 23.96 270 bottom
R92  10K  [R0402]  31.24 23.96 0 bottom
R94  1K  [R0402]  42.67 40.47 0 bottom
R95  27K  [R0402]  34.8 24.34 0 bottom
R96  10K  [R0201]  34.29 25.61 90 bottom
R101  10K  [R0201]  55.88 45.55 90 bottom
R102  10K  [R0201]  54.86 46.95 270 bottom
R103  0  [R0603]  56.01 57.78 270 bottom
R104  0  [R0603]  58.17 50.89 0 bottom
R109  10K  [R0201]  56.39 54.06 0 bottom
R110  10K  [R0201]  55.12 49.24 180 bottom
R113  12.1K  [R0402]  72.26 60.41 180 top
R114  12.1K  [R0402]  81.15 65.87 0 bottom
R117  20K  [R0402]  72.26 59.4 180 top
R118  10K  [R0201]  75.56 64.6 270 bottom
R119  20K  [R0402]  80.64 63.59 270 bottom
R120  10K  [R0201]  87 65.75 90 top
R121  9.53K  [R0402]  37.34 46.19 270 top
R122  40.2K  [R0402]  38.48 46.19 270 top
R123  0  [R0201]  79.76 52.13 180 bottom
R124  100  [R0201]  78.69 51.78 270 bottom
R125  0  [R0201]  79.76 51.42 180 bottom
R126  10K  [R0402]  33.78 49.49 0 bottom
R137  10K  [R0201]  25.91 52.54 270 top
R140  3.3K  [R0402]  40.26 41.49 0 bottom
T1  TC1-1-43A+  [AT224-1]  43.05 20.15 90 top
T2  ETC1-1-13  [ETC1]  14.99 40.03 180 bottom
T3  TCM1-43X+  [TSML150W160H160]  53.31 65.24 0 top
T4  TCM1-63AX+  [TSML150W160H160]  52.37 5.68 180 top
T5  TC1-1-43A+  [AT224-1]  37.97 51.98 90 top
T6  TCM1-63AX+  [TSML150W160H160]  21.34 33.87 90 top
TP1  TESTPAD  [TPSMC30]  51.05 29.81 0 top
TP2  TESTPAD  [TPSMC30]  60.07 31.71 270 top
TP3  TESTPAD  [TPSMC30]  38.23 16.34 0 top
TP4  TESTPAD  [TPSMC30]  32.51 15.2 90 top
TP5  TESTPAD  [TPSMC30]  60.2 10.76 90 top
TP6  TESTPAD  [TPSMC30]  60.45 29.04 90 top
TP7  TESTPAD  [TPSMC30]  55.24 30.69 90 top
TP8  TESTPAD  [TPSMC30]  73.66 40.6 90 top
TP9  TESTPAD  [TPSMC30]  12.7 62.19 0 top
TP10  TESTPAD  [TPSMC30]  50.48 42.19 0 top
TP11  TESTPAD  [TPSMC30]  66.67 60.03 0 top
TP12  TESTPAD  [TPSMC30]  75.44 64.86 270 top
TP13  TESTPAD  [TPSMC30]  66.67 63.33 270 top
TP14  TESTPAD  [TPSMC30]  7.62 38.06 0 top
TP15  TESTPAD  [TPSMC30]  22.22 46.19 270 top
TP16  TESTPAD  [TPSMC30]  12.7 7.58 90 top
TP17  TESTPAD  [TPSMC30]  44.32 46.44 180 top
TP18  TESTPAD  [TPSMC30]  58.17 41.49 270 top
TP19  TESTPAD  [TPSMC30]  56.64 41.49 270 top
TP20  TESTPAD  [TPSMC30]  108.08 40.09 180 top
TP22  TESTPAD  [TPSMC30]  41.15 61.94 0 top
TP23  TESTPAD  [TPSMC30]  35.18 30.44 0 top
TP24  TESTPAD  [TPSMC30]  33.53 36.03 0 top
TP25  TESTPAD  [TPSMC30]  68.58 60.03 0 top
TP26  TESTPAD  [TPSMC30]  104.14 59.65 0 top
TP27  TESTPAD  [TPSMC30]  108.08 37.04 180 top
TP45  TESTPAD  [TPSMC30]  108.08 47.59 270 top
TP46  TESTPAD  [TPSMC30]  108.08 38.57 270 top
TP47  TESTPAD  [TPSMC30]  102.66 32.66 270 top
TP50  TESTPAD  [TPSMC30]  108.08 54.32 180 top
TP51  TESTPAD  [TPSMC30]  108.08 52.79 180 top
TP52  TESTPAD  [TPSMC30]  108.08 44.54 180 top
TP56  TESTPAD  [TPSMC30]  108.08 49.74 180 top
TP57  TESTPAD  [TPSMC30]  108.08 51.27 180 top
U1  AD9162BBCZ  [BGA165_A]  53.72 20.34 0 top
U2  ADP2384ACPZN  [QFN24_4X4_2PAD]  75.95 32.6 90 bottom
U3  ADP2370ACPZ-R7  [QFN8_3X3_PAD2_44X1_7]  23.5 64.35 270 top
U5  ADP5073ACPZ  [QFN16_3X3_PAD1_6X1_6]  65.15 10.88 90 bottom
U6  ADP2165ACPZ-1.2  [QFN24_4X4_PAD2_5X2_5]  78.23 8.85 180 bottom
U7  ADM7154ACPZ-2.5  [DFN8_3X3_PAD2_44X1_6_A]  35.31 5.04 0 bottom
U8  M24C02-RMN6TP  [SO8]  104.78 26 0 top
U9  ADP196ACBZ  [WLCSP6]  67.94 24.98 270 bottom
U10  ADM7170ACPZ-5.0  [DFN8_3X3_PAD2_38X1_64]  7.49 14.31 90 top
U12  ADM7150ACPZ-5.0-R7  [DFN8_3X3_PAD2_38X1_64]  26.54 41.11 90 top
U13  FXL4TD245BQX  [DQFN16_3_5X2_5_PAD2_15X1_15]  105.03 38.31 270 top
U14  FXL2TD245L10X  [QFN10_2_1X1_6]  105.03 32.98 90 top
U15  ADM7170ACPZ-3.3  [DFN8_3X3_PAD2_38X1_64]  26.54 29.04 90 top
U16  ADL5240ACPZ  [QFN32_5X5_PAD3_3X3_3]  19.3 20.15 0 top
U17  ADM7170ACPZ-5.0  [DFN8_3X3_PAD2_38X1_64]  34.92 62.57 180 top
U18  ADF4355BCPZ  [QFN32_5X5_PAD3_6X3_6]  38.1 35.52 0 bottom
U19  HMC361S8GE  [S8G]  43.56 58.89 0 bottom
U20  ADM7154ACPZ-2.5  [DFN8_3X3_PAD2_44X1_6_A]  65.53 35.9 270 top
U21  ADP7182ACPZN-1.2  [DFN6_2X2_PAD1_6X1]  57.15 2.25 270 top
U22  ADM1184ARMZ  [RM10]  29.34 21.3 270 bottom
U23  FXL4T245BQX  [DQFN14_3X2_5_PAD1_65X1_15]  105.03 52.28 270 top
U24  FXL4T245BQX  [DQFN14_3X2_5_PAD1_65X1_15]  105.03 45.43 270 top
U25  HMC1119LP4ME  [LP4]  29.08 51.4 270 top
U26  AD7291BCPZ  [QFN20_4X4_PAD2_6X2_6]  104.52 13.3 90 top
U27  ADP1740ACPZ-1.2-R7  [QFN16_4X4_PAD2_1X2_1]  63.12 32.09 270 bottom
U28  ADP1761ACPZ  [QFN16_3X3_PAD1_6X1_6]  40.26 12.03 180 bottom
U101  AD9625BBPZ-2.5  [BGA196H67]  53.21 50.38 0 top
VR1  ADP1741ACPZ  [QFN16_4X4_PAD2_1X2_1]  72.26 62.32 0 bottom
VR2  ADP1741ACPZ  [QFN16_4X4_PAD2_1X2_1]  83.69 63.59 90 top
VR3  ADP1741ACPZ  [QFN16_4X4_PAD2_1X2_1]  35.43 45.93 90 bottom
Y1  122.88MEGHZ  [YSML276W197H63]  22.79 34.12 90 bottom

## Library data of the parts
C1-C3 C19 C20 = CAP: Tolerance: 5; User Part Number: UPN; alternate symbols: C0402_ALT; part number: CAP_SM-100PF,50V,5,E024302,C0402; tolerance: 5; signal model: DEFAULT_CAPACITOR_100000pF_1_2
C4 C81 C327 C328 C330 C332 = CAP: Tolerance: 5; User Part Number: UPN; alternate symbols: C0402_ALT; part number: CAP_SM-10PF,50V,5,E007982,C0402; tolerance: 5
C5 C100 C105 C107-C116 C118 C120 C121 C123 C124 C130-C138 C141 C144 C196-C200 C257-C264 C266-C309 C326 C329 C331 = CAP: alternate symbols: (); part number: CAP_SM-0.1UF,16V,20,E017331,C0201; tolerance: 20
C6 C46 C47 C66 C70 C74 C80 C145 C146 C245 C248 C310 C334 = CAP: Tolerance: 10; User Part Number: UPN; alternate symbols: C0402_ALT; part number: CAP_SM-1UF,16V,10,E033911,C0402; tolerance: 10
C7 C149 C155 C323 C337 = CAP: Tolerance: 5; User Part Number: UPN; alternate symbols: C0402_ALT; part number: CAP_SM-100PF,50V,5,E024302,C0402; tolerance: 5
C8 C9 C14 C15 C17 = CAP: alternate symbols: (); part number: CAP_SM-0.1UF,16V,20,E017331,C0201; tolerance: 20; signal model: DEFAULT_CAPACITOR_100000pF_1_2
C10 = CAP: Tolerance: 10; User Part Number: UPN; alternate symbols: C0402_ALT; part number: CAP_SM-1UF,16V,10,E033911,C0402; tolerance: 10; signal model: DEFAULT_CAPACITOR_100000pF_1_2
C11 C12 C242 C265 = CAP: Tolerance: 0.1pF; User Part Number: UPN; alternate symbols: C0201-2; part number: CAP_SM-0.6PF,25V,0.1PF,E023656,C0201; tolerance: 0.1pF
C13 C36 C314 C315 = CAP: alternate symbols: (); part number: CAP_SM-100PF,25V,10,E006763,C0201; tolerance: 10
C16 = CAP: Tolerance: 5; User Part Number: UPN; alternate symbols: C0402_ALT; part number: CAP_SM-10PF,50V,5,E007982,C0402; tolerance: 5; signal model: DEFAULT_CAPACITOR_100000pF_1_2
C18 = CAP: Tolerance: 10; User Part Number: UPN; alternate symbols: C0603L_ALT; part number: CAP_SM-0.01UF,50V,10,E017640,C0603; tolerance: 10; signal model: capacitor20pF
C21 C41 = CAP: alternate symbols: (); part number: CAP_SM-0.001UF,25V,10,E006762,C0201; tolerance: 10; signal model: DEFAULT_CAPACITOR_100000pF_1_2
C22 = CAP: Tolerance: 20; User Part Number: UPN; alternate symbols: (); part number: CAP_SM-22UF,10V,20,E032369,C0805H60; tolerance: 20; signal model: DEFAULT_CAPACITOR_100000pF_1_2
C23 = CAP: Tolerance: 20; User Part Number: UPN; alternate symbols: (); part number: CAP_SM-22UF,25V,20,E032575,C0805H60; tolerance: 20; signal model: DEFAULT_CAPACITOR_100000pF_1_2
C24 = CAP: Tolerance: 5; User Part Number: UPN; alternate symbols: (); part number: CAP_SM-68PF,50V,5,E033338,C0402; tolerance: 5
C25 = CAP: Tolerance: 10; User Part Number: UPN; alternate symbols: (); part number: CAP_SM-0.1UF,10V,10,E007265,C0402; tolerance: 10; signal model: DEFAULT_CAPACITOR_100000pF_1_2
C26 = CAP: Tolerance: 10; User Part Number: UPN; alternate symbols: (); part number: CAP_SM-0.022UF,16V,10,E000327,C0603; tolerance: 10; signal model: DEFAULT_CAPACITOR_100000pF_1_2
C27 C154 C156 = CAP: Tolerance: 10; User Part Number: UPN; alternate symbols: (); part number: CAP_SM-10UF,16V,10,E006166,C0805H53; tolerance: 10
C28 = CAP: Tolerance: 10; User Part Number: UPN; alternate symbols: C0402_ALT; part number: CAP_SM-0.056UF,16V,10,E023842,C0402; tolerance: 10
C29 = CAP: Tolerance: 5; User Part Number: UPN; alternate symbols: C0402_ALT; part number: CAP_SM-220PF,50V,5,E018153,C0402; tolerance: 5
C30 C73 C90 C92 C94 C97 C98 C103 C125 C126 = CAP: Tolerance: 10; User Part Number: UPN; alternate symbols: (); part number: CAP_SM-0.1UF,10V,10,E007265,C0402; tolerance: 10
C31 = CAP: Tolerance: 10; User Part Number: UPN; alternate symbols: C0402_ALT; part number: CAP_SM-1UF,10V,10,E033897,C0402; tolerance: 10
C32 C34 C44 C104 C333 C338 = CAP: alternate symbols: (); part number: CAP_SM-0.001UF,25V,10,E006762,C0201; tolerance: 10
C33 = CAP: Tolerance: 10; User Part Number: UPN; alternate symbols: (); part number: CAP_SM-0.01UF,25V,10,E013688,C0402; tolerance: 10
C35 = CAP: alternate symbols: C0201-2; part number: CAP_SM-680PF,16V,10,E012328,C0201; tolerance: 10
C37 = CAP: Tolerance: 10; User Part Number: UPN; alternate symbols: (); part number: CAP_SM-0.0068UF,50V,10,E005338,C0603; tolerance: 10
C38 C43 C45 C50 = CAP: Tolerance: 20; User Part Number: UPN; alternate symbols: (); part number: CAP_SM-22UF,16V,20,E013399,C1206H71; tolerance: 20
C39 C58 C61 = CAP: Tolerance: 20; User Part Number: UPN; alternate symbols: (); part number: CAP_SM-0.1UF,25V,20,E000372,C0603H62; tolerance: 20
C40 = CAP: Tolerance: 5; User Part Number: UPN; alternate symbols: C0402_ALT; part number: CAP_SM-100PF,50V,5,E022402,C0402; tolerance: 5; signal model: DEFAULT_CAPACITOR_100000pF_1_2
C42 C52-C54 = CAP: Tolerance: 20; User Part Number: UPN; alternate symbols: (C0805L); part number: CAP_SM-47UF,6.3V,20,E008247,C0805H60; tolerance: 20
C48 C62 C65 C67 C69 C72 = CAP: Tolerance: 20; User Part Number: UPN; alternate symbols: (); part number: CAP_SM-22UF,10V,20,E032369,C0805H60; tolerance: 20
C49 C78 C79 C122 C183 C185 = CAP: Tolerance: 10; User Part Number: UPN; alternate symbols: C0402_ALT; part number: CAP_SM-0.47UF,10V,10,E007611,C0402; tolerance: 10
C51 = CAP: Tolerance: 20; User Part Number: UPN; alternate symbols: (); part number: CAP_SM-100UF,6.3V,20,E016591,C1206H71; tolerance: 20
C55 = CAP: Tolerance: 10; User Part Number: UPN; alternate symbols: (); part number: CAP_SM-0.022UF,16V,10,E000327,C0603; tolerance: 10
C56 = CAP: Tolerance: 20; User Part Number: UPN; alternate symbols: (); part number: CAP_SM-47UF,10V,20,E022064,C0805H60; tolerance: 20
C57 = CAP: Tolerance: 20; User Part Number: UPN; alternate symbols: (); part number: CAP_SM-10UF,6.3V,20,E025398,C0603; tolerance: 20
C59 = CAP: Tolerance: 10; User Part Number: UPN; alternate symbols: C0402_ALT; part number: CAP_SM-1UF,6.3V,10,E011561,C0402; tolerance: 10
C60 = CAP: Tolerance: 10; User Part Number: UPN; alternate symbols: C0402_ALT; part number: CAP_SM-470PF,25V,10,E012313,C0402; tolerance: 10
C63 C68 C77 C84 C87-C89 C95 C102 C139 C140 C143 C147 C148 C151-C153 C157 C229-C233 C247 C250-C253 C311 C312 C321 = CAP: Tolerance: 20; User Part Number: UPN; alternate symbols: (); part number: CAP_SM-10UF,10V,20,E018646,C0603; tolerance: 20
C64 = CAP: Tolerance: 10; User Part Number: UPN; alternate symbols: (); part number: CAP_SM-0.0022UF,50V,10,E007460,C0402; tolerance: 10
C71 = CAP: Tolerance: 5; User Part Number: UPN; alternate symbols: C0402_ALT; part number: CAP_SM-100PF,50V,5,E033811,C0402; tolerance: 5
C75 = CAP: Tolerance: 5; User Part Number: UPN; alternate symbols: C0402_ALT; part number: CAP_SM-1.5NF,50V,5,E033272,C0402; tolerance: 5
C76 = CAP: Tolerance: 10; User Part Number: UPN; alternate symbols: C0402_ALT; part number: CAP_SM-0.033UF,50V,10,E019776,C0402; tolerance: 10
C82 C85 C313 C341 = CAP: Tolerance: 20; User Part Number: UPN; alternate symbols: C0603L_ALT; part number: CAP_SM-10UF,10V,20,E018646,C0603; tolerance: 20
C83 C91 C93 C96 C158-C160 C164 C234-C238 C254-C256 C322 C335 C339 C340 = CAP: Tolerance: 10; User Part Number: UPN; alternate symbols: C0402_ALT; part number: CAP_SM-0.1UF,25V,10,E026964,C0402; tolerance: 10
C86 = CAP: Tolerance: 10; User Part Number: UPN; alternate symbols: C0603L_ALT; part number: CAP_SM-0.01UF,50V,10,E017640,C0603; tolerance: 10
C99 C101 C106 C117 C119 C142 C150 C205 C206 C227 C228 C244 C249 C316 C317 = CAP: Tolerance: 10; User Part Number: UPN; alternate symbols: (); part number: CAP_SM-4.7UF,16V,10,E020112,C0603; tolerance: 10
C127 C186 C187 C201-C203 C318-C320 = CAP: alternate symbols: C0201-2; part number: CAP_SM-0.1UF,16V,20,E017331,C0201; tolerance: 20
C128 = CAP: Tolerance: 10; User Part Number: UPN; alternate symbols: (); part number: CAP_SM-4.7UF,6.3V,10,E010382,C0603; tolerance: 10
C129 = CAP: Tolerance: 10; User Part Number: UPN; alternate symbols: C0402_ALT; part number: CAP_SM-0.1UF,16V,10,E027519,C0402; tolerance: 10
C161 C163 = CAP: Tolerance: 20; User Part Number: UPN; alternate symbols: (); part number: CAP_SM-47UF,16V,20,E033215,C1206H71; tolerance: 20
C165-C180 C190 C191 C204 C208-C223 C239 C240 = CAP: alternate symbols: (); part number: CAP_SM-0.001UF,25V,10,E006762,C0201; tolerance: 10; signal model: capacitor20pF
C184 = CAP: Tolerance: 10; User Part Number: UPN; alternate symbols: C0402_ALT; part number: CAP_SM-0.47UF,10V,10,E007611,C0402; tolerance: 10; signal model: DEFAULT_CAPACITOR_100000pF_1_2
C188 C189 = CAP: alternate symbols: (); part number: CAP_SM-1PF,25V,0.25PF,E012874,C0201; tolerance: 0.25pF
C194 = CAP: Tolerance: 10; User Part Number: UPN; alternate symbols: C0603L_ALT; part number: CAP_SM-4.7UF,6.3V,10,E010382,C0603; tolerance: 10; signal model: DEFAULT_CAPACITOR_100000pF_1_2
C195 = CAP: Tolerance: 10; User Part Number: UPN; alternate symbols: C0603L_ALT; part number: CAP_SM-0.01UF,50V,10,E017640,C0603; tolerance: 10; signal model: DEFAULT_CAPACITOR_1000pF_1_2
C207 C226 C246 = CAP: alternate symbols: (); part number: CAP_SM-0.01UF,10V,10,E007201,C0201; tolerance: 10
C241 = CAP: Tolerance: 10; User Part Number: UPN; alternate symbols: C0603L_ALT; part number: CAP_SM-4.7UF,6.3V,10,E010382,C0603; tolerance: 10
C243 = CAP: Tolerance: 20; User Part Number: UPN; alternate symbols: (); part number: CAP_SM-10UF,10V,20,E018646,C0603; tolerance: 20; signal model: DEFAULT_CAPACITOR_100000pF_1_2
C324 = CAP: alternate symbols: C0201-2; part number: CAP_SM-100PF,25V,10,E006763,C0201; tolerance: 10
C336 = CAP: Tolerance: 5; User Part Number: UPN; alternate symbols: C0402_ALT; part number: CAP_SM-390PF,50V,5,E033837,C0402; tolerance: 5
CR5 = DIOLED: Tolerance: N/A; User Part Number: UPN; alternate symbols: (); part number: DIOLED_SM-LG L29K-G2J1-24-Z,N/A,N/A,E010948,LED0603-2; tolerance: N/A
D2 = DIOSCHOTTKY: Tolerance: N/A; User Part Number: UPN; alternate symbols: (SOD882L_ALT); part number: DIOSCHOTTKY_SM-PMEG2005AEL,315,20V,N/A,E021538,SOD882; tolerance: N/A
DS1 = DIOLED: User Part Number: UPN; Tolerance: N/A; alternate symbols: (); part number: DIOLED_SM-SML-E12M8WT86,2.2V,N/A,E024936,LED0603_A; tolerance: N/A
DS2 = DIOLED: User Part Number: UPN; Tolerance: N/A; alternate symbols: (); part number: DIOLED_SM-SML-P11MTT86,N/A,N/A,E014445,LED0402; tolerance: N/A
E1 E2 = FERRITE: Tolerance: 5; User Part Number: UPN; alternate symbols: (); part number: FERRITE_SM-270NH,5,E018219,L0402-2; tolerance: 5
E3 E6-E9 E15-E18 E22-E30 = FERRITE: Tolerance: 25; User Part Number: UPN; alternate symbols: (); part number: FERRITE_SM-42OHM AT 100MEGHZ,25,E022207,L0805; tolerance: 25
E4 = RES: Tolerance: 1; User Part Number: UPN; alternate symbols: R0603_A; part number: RES_SM-0,E004207,1/16W,1,R0603; tolerance: 1
E5 = FERRITE: Tolerance: 5; User Part Number: UPN; alternate symbols: (); part number: FERRITE_SM-33NH,5,E025525,L0402-2; tolerance: 5
E12-E14 E21 R103 R104 = RES: Tolerance: 1; User Part Number: UPN; alternate symbols: (R0603L); part number: RES_SM-0,E004207,1/16W,1,R0603; tolerance: 1
FL1 = FLTRBP4P: Tolerance: N/A; User Part Number: UPN; alternate symbols: (); part number: FLTRBP4P_SM-4400MEGHZ,E020599,FLSML126W63H37-2; tolerance: N/A
J1-J3 J5 J7 = CNBNC3P: User Part Number: UPN; Tolerance: N/A; alternate symbols: (); part number: CNBNC3P_SM-142-0711-201,E000902,CNJOHNSON142-0711-201; tolerance: N/A
J4 J6 = CNBNC5P: Tolerance: N/A; User Part Number: UPN; alternate symbols: (); part number: CNBNC5P_SM-142-0701-851,E014551,CNSMAL562W375H166; tolerance: N/A
JP1 JP2 = NC3P_JMPR: Tolerance: N/A; User Part Number: UPN; alternate symbols: (); part number: NC3P_JMPR_SM-3PIN_SOLDER_JUMPER,E005606,JPRSLD03; tolerance: N/A
JP3-JP5 JP22 = NC3P_JMPR: Tolerance: N/A; User Part Number: UPN; alternate symbols: (); part number: NC3P_JMPR_SM-3PIN_JUMPER,E006495,3PINJUMPER_0402; tolerance: N/A
L1 = IND: Tolerance: 20; User Part Number: UPN; alternate symbols: (); part number: IND_SM-2.2UH,20,E025569,L0805_A; tolerance: 20
L2 = IND: User Part Number: UPN; Tolerance: 20; alternate symbols: (); part number: IND_SM-10UH,20,E025494,LSMSQ189H123; tolerance: 20
L3 = IND: User Part Number: UPN; Tolerance: 20; alternate symbols: (); part number: IND_SM-1.5UH,20,E017267,LSMSQ157H83; tolerance: 20
L4 = IND: Tolerance: 20; User Part Number: UPN; alternate symbols: (); part number: IND_SM-0.68UH,20,E025495,L1008H47; tolerance: 20
L5 = IND: User Part Number: UPN; Tolerance: 20; alternate symbols: (); part number: IND_SM-0.33UH,20,E024488,LSMSQ154H47_A; tolerance: 20
L6 = IND: Tolerance: 20; User Part Number: UPN; alternate symbols: (); part number: IND_SM-0.47UH,20,E025526,L7144; tolerance: 20
L7 = IND: Tolerance: 5; User Part Number: UPN; alternate symbols: (L0603L); part number: IND_SM-470NH,5,E007703,L0603; tolerance: 5
L8 = IND: Tolerance: 20; User Part Number: UPN; alternate symbols: (); part number: IND_SM-0.33UH,20,E025493,LSMSQ118H47; tolerance: 20
L13-L16 = IND: Tolerance: 0.3NH; User Part Number: UPN; alternate symbols: (); part number: IND_SM-1.5NH,0.3NH,E025727,L0201H13; tolerance: 0.3NH
P1 = CN400P_A_K_V2: User Part Number: UPN; Tolerance: N/A; alternate symbols: (); part number: CN400P_A_K_V2_SM-ASP-134488-01,E011384,CNSAMTECASP-134488-01; tolerance: N/A
Q1 = TRAN2N7002: User Part Number: UPN; Tolerance: N/A; alternate symbols: (); part number: TRAN2N7002_SM-2N7002T,E030709,SOT523F; tolerance: N/A
Q4 = TRANNMOSFET_V15: Tolerance: N/A; User Part Number: UPN; alternate symbols: (); part number: TRANNMOSFET_V15_SM-SI7102DN-T1-GE3,E022830,Q1212-8P; tolerance: N/A
R1 = RES: Tolerance: 1; User Part Number: UPN; alternate symbols: R0402_ALT; part number: RES_SM-6.04K,E004030,1/16W,1,R0402; tolerance: 1; signal model: DEFAULT_RESISTOR_0.001OHM_1_2
R2 = RES: Tolerance: 1; User Part Number: UPN; alternate symbols: R0402_ALT; part number: RES_SM-100K,E003796,1/16W,1,R0402; tolerance: 1
R3 = RES: Tolerance: 1; User Part Number: UPN; alternate symbols: (R0603L); part number: RES_SM-36.5K,E011130,1/10W,1,R0603; tolerance: 1
R4 = RES: Tolerance: 1; User Part Number: UPN; alternate symbols: (R0603L); part number: RES_SM-210K,E017262,1/10W,1,R0603; tolerance: 1
R5 R79 R82 R96 R101 R102 R109 R110 R118 R120 R137 = RES: alternate symbols: (); part number: RES_SM-10K,E004011,1/20W,1,R0201; tolerance: 1
R6 R36 R45 R56 R64 R94 = RES: Tolerance: 1; User Part Number: UPN; alternate symbols: R0402_ALT; part number: RES_SM-1K,E003763,1/10W,1,R0402; tolerance: 1
R7 = RES: Tolerance: 1; User Part Number: UPN; alternate symbols: R0402_ALT; part number: RES_SM-9.76K,E010026,1/16W,1,R0402; tolerance: 1; signal model: DEFAULT_RESISTOR_0.001OHM_1_2
R8 = RES: alternate symbols: (); part number: RES_SM-100,E007239,1/20W,1,R0201; tolerance: 1; signal model: DEFAULT_RESISTOR_0.001OHM_1_2
R9 = RES: Tolerance: 1; User Part Number: UPN; alternate symbols: R0402_ALT; part number: RES_SM-5.1K,E019615,1/16W,1,R0402; tolerance: 1
R10 R33 = RES: alternate symbols: (); part number: RES_SM-130,E019677,1/20W,5,R0201; tolerance: 5
R11 = RES: Tolerance: 1; User Part Number: UPN; alternate symbols: R0402_ALT; part number: RES_SM-140,E006740,1/16W,1,R0402; tolerance: 1
R12 R73 = RES: alternate symbols: (); part number: RES_SM-82,E026688,1/20W,1,R0201; tolerance: 1
R13 R52-R54 R92 R126 = RES: User Part Number: UPN; Tolerance: 1; alternate symbols: (R0402L,R0402L_ALT); part number: RES_SM-10K,E003751,1/10W,1,R0402; tolerance: 1
R14 = RES: Tolerance: 0.1; User Part Number: UPN; alternate symbols: R0402_ALT; part number: RES_SM-4.99K,E012476,1/16W,0.1,R0402; tolerance: 0.1
R15 = RES: Tolerance: 1; User Part Number: UPN; alternate symbols: (R0603L); part number: RES_SM-10K,E017856,1/16W,1,R0603; tolerance: 1
R16 = RES: Tolerance: 1; User Part Number: UPN; alternate symbols: (R0603L); part number: RES_SM-15K,E004211,1/16W,1,R0603; tolerance: 1
R17 = RES: Tolerance: 0.1; User Part Number: UPN; alternate symbols: (R0603L); part number: RES_SM-50K,E020895,0.15W,0.1,R0603; tolerance: 0.1
R18 = RES: Tolerance: 1; User Part Number: UPN; alternate symbols: R0402_ALT; part number: RES_SM-4.22K,E007509,1/16W,1,R0402; tolerance: 1
R19 = RES: Tolerance: 1; User Part Number: UPN; alternate symbols: R0402_ALT; part number: RES_SM-115K,E025179,1/10W,1,R0402; tolerance: 1
R20 = RES: Tolerance: 1; User Part Number: UPN; alternate symbols: R0402_ALT; part number: RES_SM-7.5K,E023755,1/10W,1,R0402; tolerance: 1
R21 R28 = RES: Tolerance: 1; User Part Number: UPN; alternate symbols: R0402_ALT; part number: RES_SM-10,E017858,1/16W,1,R0402; tolerance: 1
R22-R27 R61 R72 R75 R76 R83 R85 R91 R123 R125 = RES: alternate symbols: (); part number: RES_SM-0,E004015,1/20W,0,R0201; tolerance: N/A
R29 = RES: Tolerance: 1; User Part Number: UPN; alternate symbols: (R0603L); part number: RES_SM-6.04K,E013310,1/10W,1,R0603; tolerance: 1
R30 = RES: Tolerance: 5; User Part Number: UPN; alternate symbols: R0402_ALT; part number: RES_SM-10K,E019640,1/16W,5,R0402; tolerance: 5
R31 R89 R124 = RES: alternate symbols: (); part number: RES_SM-100,E007239,1/20W,1,R0201; tolerance: 1
R32 = RES: Tolerance: 5; User Part Number: UPN; alternate symbols: R0402_ALT; part number: RES_SM-300,E003444,1/16W,5,R0402; tolerance: 5
R34 R35 R40 R47 R66 R67 = RES: Tolerance: 1; User Part Number: UPN; alternate symbols: R0402_ALT; part number: RES_SM-4.02K,E004026,1/16W,1,R0402; tolerance: 1
R37 = RES: alternate symbols: (); part number: RES_SM-51,E006644,1/20W,1,R0201; tolerance: 1
R38 R50 = RES: Tolerance: 1; User Part Number: UPN; alternate symbols: R0402_ALT; part number: RES_SM-6.04K,E004030,1/16W,1,R0402; tolerance: 1
R39 = RES: Tolerance: 1; User Part Number: UPN; alternate symbols: R0402_ALT; part number: RES_SM-25.5K,E006354,1/16W,1,R0402; tolerance: 1
R41 R42 = RES: Tolerance: 1; User Part Number: UPN; alternate symbols: R0402_ALT; part number: RES_SM-33,E020519,1/10W,1,R0402; tolerance: 1
R43 R48 = RES: Tolerance: 5; User Part Number: UPN; alternate symbols: R0402_ALT; part number: RES_SM-3K,E008023,1/16W,5,R0402; tolerance: 5
R44 R46 R49 = RES: Tolerance: 1; User Part Number: UPN; alternate symbols: R0402_ALT; part number: RES_SM-1.2K,E007439,1/16W,1,R0402; tolerance: 1
R51 R65 = RES: Tolerance: 1; User Part Number: UPN; alternate symbols: R0402_ALT; part number: RES_SM-2.26K,E020474,1/10W,1,R0402; tolerance: 1
R55 = RES: Tolerance: 1; User Part Number: UPN; alternate symbols: R0402_ALT; part number: RES_SM-6.34K,E003777,1/16W,1,R0402; tolerance: 1
R57 R58 R62 R63 = RES: alternate symbols: (); part number: RES_SM-10,E013982,1/20W,1,R0201; tolerance: 1
R59 R60 R69 R70 = RES: alternate symbols: (); part number: RES_SM-33,E011241,1/20W,1,R0201; tolerance: 1
R68 = RES: Tolerance: 1; User Part Number: UPN; alternate symbols: R0402_ALT; part number: RES_SM-80.6K,E006346,1/16W,1,R0402; tolerance: 1
R71 R78 = RES: Tolerance: 1; User Part Number: UPN; alternate symbols: R0402_ALT; part number: RES_SM-115,E016405,1/10W,1,R0402; tolerance: 1
R77 = RES: Tolerance: 1; User Part Number: UPN; alternate symbols: R0402_ALT; part number: RES_SM-52.3,E003762,1/16W,1,R0402; tolerance: 1
R80 R81 = RES: alternate symbols: (); part number: RES_SM-0,E004015,1/20W,0,R0201; tolerance: N/A; signal model: DEFAULT_RESISTOR_0.001OHM_1_2
R84 = RES: Tolerance: 0.1; User Part Number: UPN; alternate symbols: R0402_ALT; part number: RES_SM-8.06K,E011896,1/16W,0.1,R0402; tolerance: 0.1
